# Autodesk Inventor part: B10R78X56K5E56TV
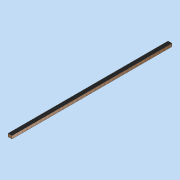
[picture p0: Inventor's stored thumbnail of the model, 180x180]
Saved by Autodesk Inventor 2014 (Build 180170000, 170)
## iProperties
Created: 2011-08
Part Number: B10R78X56K5E56TV
Document SubType Name: Modeling
Designer: david.appleford
Density: 0.432775 g/cm^3
Description: Roof Edge Beam 2.5w - 5 Locks Ext 56mm + 68mm
Mass: 6000 g
Surface Area: 8593.68 cm^2
Volume: 13864 cm^3
Cost Center: £33.00
Material: 000 Redwood
Appearance: Wood (Oak)
Justset: False
Title: Roof Edge Beam 2.5w - 5 Locks
Author: david.appleford
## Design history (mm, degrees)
sketch "Sketch1"
  geometry: L1 (39, -34)-(-39, -34); L2 (-39, -34)-(-39, 3140); L3 (-39, 3140)-(39, 3140); L4 (39, 3140)-(39, -34); 1 further point
  constraints: 8 end point, 2 parallel, 1 horizontal, 1 perpendicular, 1 other
  dimensions: "d2" = 78 distance between parallel lines of L2 L4; "d3" = 34 distance from line of point (0, 0) L1; "d4" = 39 distance from line of point (0, 0) L2 (= 0.5 x d2); "d5" = 3174 distance of L3.end L1.start
extrude "Extrusion1" new body sketch "Sketch1" distance "d0" = 56; taper "d1" = 0 deg
body "Solid1"
